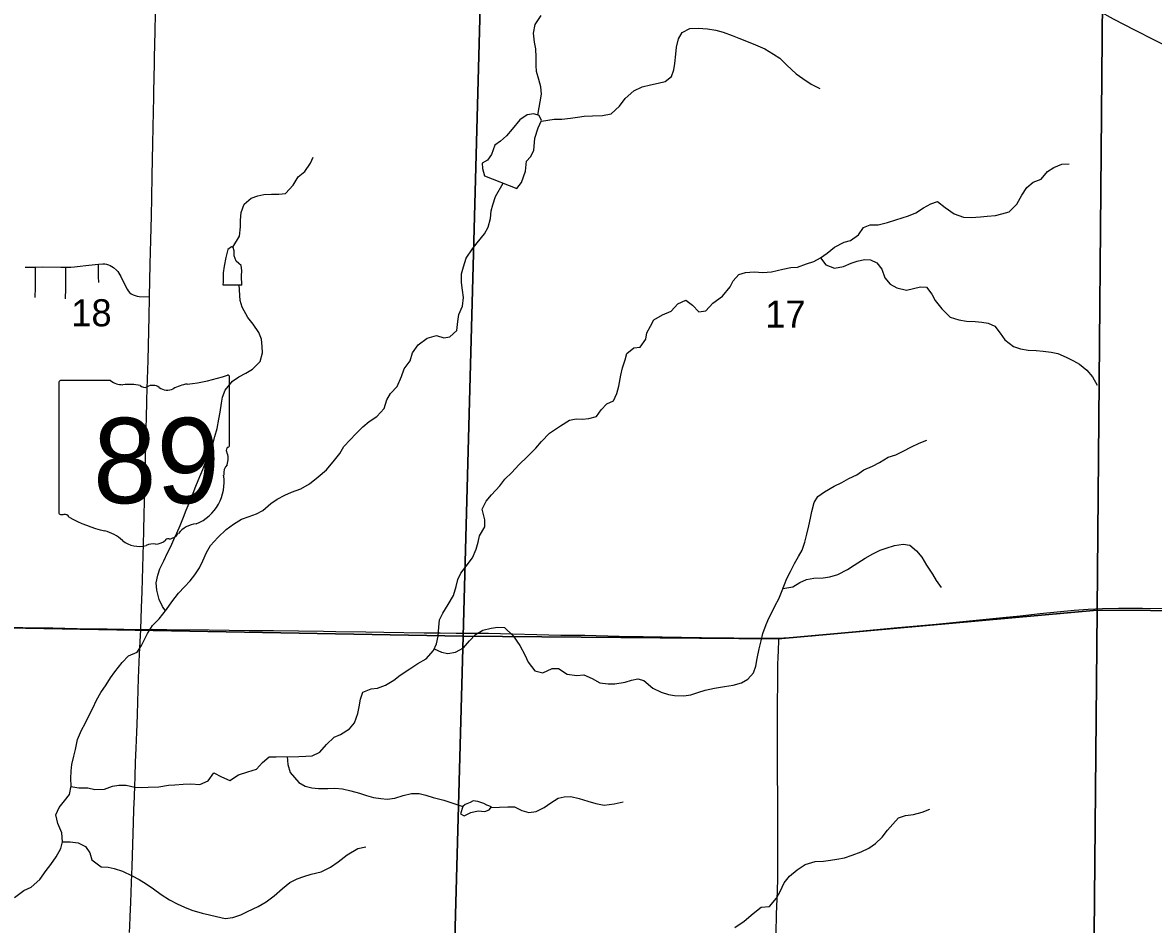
# Model space of a CAD drawing. Extents: x 0 to 34, y 0 to 22.
# Drawn here: x 11.919 to 13.666, y 9.788 to 11.182 of the extents above; entities that cross this region are included whole.
import ezdxf

# ---------------------------------------------------------------- set-up
doc = ezdxf.new("R2010")
doc.units = 0
for name, color, linetype in [('GM_X_County_Road', 7, 'Continuous'), ('GM_X_Minor_Lake', 7, 'Continuous'), ('GM_X_Minor_River', 7, 'Continuous'), ('GM_X_Section', 7, 'Continuous'), ('GM_X_Section_Text', 7, 'Continuous'), ('GM_X_State_Route', 7, 'Continuous'), ('GM_X_State_Shield', 7, 'Continuous'), ('GM_X_Township_Road', 7, 'Continuous'), ('GM_X_US_Route', 7, 'Continuous')]:
    doc.layers.add(name, color=color, linetype=linetype)

msp = doc.modelspace()

# ---------------------------------------------------------------- linework, layer by layer
at = {"layer": 'GM_X_County_Road'}
msp.add_lwpolyline([(13.4671, 11.2609), (13.4723, 11.2592), (13.478, 11.2569), (13.4823, 11.2551), (13.4923, 11.2503), (13.506, 11.243), (13.5275, 11.2307), (13.5572, 11.2137), (13.5814, 11.1998), (13.6032, 11.1878), (13.6363, 11.1705), (13.6668, 11.1552), (13.6919, 11.1429), (13.762, 11.1094), (13.8094, 11.0862), (13.843, 11.07), (13.8851, 11.05), (13.9075, 11.0392), (13.9465, 11.0201), (13.9745, 11.0065), (14.0109, 10.989), (14.0473, 10.9715), (14.078, 10.9566), (14.0833, 10.954)], dxfattribs=at)
at = {"layer": 'GM_X_Minor_Lake'}
for points in [[(12.6823, 10.9255), (12.6891, 10.9346), (12.6955, 10.9521), (12.6969, 10.9676), (12.7034, 10.9745), (12.7083, 10.984), (12.7097, 11.0029), (12.715, 11.0193), (12.7203, 11.0303), (12.7168, 11.0383), (12.7081, 11.0409), (12.6979, 11.039), (12.6869, 11.0317), (12.6748, 11.0169), (12.6661, 11.0066), (12.657, 10.9986), (12.6479, 10.9925), (12.6427, 10.9781), (12.6366, 10.969), (12.6287, 10.9644), (12.6291, 10.9564), (12.6321, 10.945)], [(12.6321, 10.945), (12.6823, 10.9255)], [(12.2571, 10.7763), (12.2567, 10.7898), (12.257, 10.7989), (12.2562, 10.8062), (12.2524, 10.8096), (12.2483, 10.8133), (12.2456, 10.8213), (12.2452, 10.8289), (12.244, 10.8342), (12.2414, 10.8353), (12.2357, 10.8311), (12.2323, 10.819), (12.2297, 10.8053), (12.2282, 10.7951), (12.2283, 10.7806)], [(12.2571, 10.7762), (12.2567, 10.7898), (12.257, 10.7989), (12.2562, 10.8062), (12.2524, 10.8096), (12.2483, 10.8133), (12.2456, 10.8213), (12.2452, 10.8289), (12.244, 10.8342), (12.2414, 10.8353), (12.2357, 10.8311), (12.2323, 10.819), (12.2297, 10.8053), (12.2282, 10.7951), (12.2283, 10.7806)], [(12.2283, 10.7806), (12.228, 10.7764), (12.2571, 10.7763)], [(12.61, 9.9768), (12.6024, 9.9736), (12.5986, 9.9705), (12.5952, 9.9592), (12.6009, 9.9558), (12.6108, 9.9611), (12.6225, 9.9638), (12.6324, 9.9627), (12.6392, 9.965), (12.643, 9.9699), (12.6358, 9.9726)], [(12.6358, 9.9726), (12.6309, 9.9752), (12.6265, 9.9766), (12.6217, 9.9781), (12.6144, 9.9789), (12.61, 9.9768)]]:
    msp.add_lwpolyline(points, dxfattribs=at)
at = {"layer": 'GM_X_Minor_River'}
for points in [[(12.7147, 11.0389), (12.7202, 11.0709), (12.719, 11.0823), (12.7159, 11.0936), (12.7125, 11.1062), (12.7117, 11.1156), (12.712, 11.1285), (12.7112, 11.1411), (12.7093, 11.1517), (12.7077, 11.1653), (12.7104, 11.1786), (12.7198, 11.1927)], [(12.72, 11.0296), (12.7396, 11.0326), (12.7518, 11.0327), (12.765, 11.0342), (12.7756, 11.0358), (12.7859, 11.0369), (12.7988, 11.0377), (12.8143, 11.0382), (12.8276, 11.0409), (12.8405, 11.0527), (12.8492, 11.0645), (12.8628, 11.0763), (12.8757, 11.0824), (12.8886, 11.0858), (12.9003, 11.0881), (12.9113, 11.0908), (12.9211, 11.0984), (12.9245, 11.1087), (12.926, 11.1186), (12.9275, 11.133), (12.929, 11.144), (12.932, 11.1565), (12.9376, 11.1664), (12.9494, 11.1725), (12.9623, 11.1729), (12.9767, 11.1722), (12.9896, 11.17), (13.001, 11.167), (13.015, 11.1617), (13.0253, 11.1576), (13.0371, 11.1531), (13.0507, 11.1474), (13.0652, 11.141), (13.0785, 11.1331), (13.0884, 11.127), (13.0994, 11.1161), (13.1138, 11.1028), (13.1237, 11.0956), (13.137, 11.0866), (13.1503, 11.0798)], [(12.2432, 10.8345), (12.2535, 10.8517), (12.2553, 10.8661), (12.2553, 10.8763), (12.2564, 10.8881), (12.2609, 10.901), (12.2715, 10.9102), (12.2817, 10.914), (12.2912, 10.9159), (12.303, 10.9167), (12.3143, 10.9167), (12.3246, 10.9179), (12.3363, 10.9305), (12.3442, 10.9434), (12.3544, 10.9518), (12.3635, 10.9643), (12.3673, 10.9738)], [(12.9309, 10.7471), (12.9434, 10.7528), (12.9533, 10.7449), (12.9632, 10.7347), (12.9742, 10.7362), (12.9848, 10.748), (12.9999, 10.7591), (13.0116, 10.7732), (13.0165, 10.7827), (13.0248, 10.7926), (13.0355, 10.7956), (13.0487, 10.7964), (13.062, 10.7957), (13.0753, 10.7965), (13.0931, 10.8007), (13.1056, 10.8034), (13.1159, 10.8038), (13.1295, 10.8088), (13.1409, 10.8126), (13.1511, 10.8184), (13.1613, 10.8252), (13.173, 10.8347), (13.1878, 10.8424), (13.1977, 10.8451), (13.2098, 10.8538), (13.2177, 10.8649), (13.228, 10.8691), (13.2405, 10.8691), (13.2549, 10.8726), (13.2674, 10.8768), (13.2776, 10.8798), (13.2871, 10.8829), (13.2985, 10.8879), (13.3106, 10.8955), (13.3216, 10.9016), (13.3318, 10.9054), (13.344, 10.896), (13.3576, 10.8861), (13.3721, 10.8809), (13.3842, 10.8805), (13.3983, 10.8817), (13.4085, 10.8825), (13.4218, 10.8837), (13.4312, 10.886), (13.4426, 10.8894), (13.4547, 10.9012), (13.4623, 10.9149), (13.4698, 10.9267), (13.48, 10.9351), (13.4922, 10.9397), (13.502, 10.9518), (13.5118, 10.9579), (13.5243, 10.9629), (13.5353, 10.9633)], [(12.5437, 10.694), (12.5578, 10.6982), (12.5692, 10.6948), (12.5786, 10.6963), (12.5892, 10.7062), (12.5907, 10.7199), (12.5926, 10.7305), (12.5982, 10.7438), (12.5997, 10.7571), (12.5981, 10.7681), (12.5966, 10.7799), (12.5966, 10.7935), (12.5996, 10.8045), (12.6037, 10.8178), (12.6135, 10.8319), (12.6207, 10.8414), (12.632, 10.8551), (12.6377, 10.8654), (12.6414, 10.879), (12.6425, 10.8908), (12.6448, 10.9003), (12.6493, 10.9128), (12.6612, 10.9337)], [(13.1511, 10.8184), (13.1595, 10.8074), (13.1731, 10.8025), (13.1868, 10.8048), (13.1985, 10.8098), (13.208, 10.8132), (13.219, 10.8159), (13.2285, 10.8152), (13.238, 10.8107), (13.246, 10.8008), (13.2506, 10.7875), (13.2586, 10.7773), (13.2692, 10.7717), (13.284, 10.7683), (13.295, 10.7706), (13.3056, 10.7733), (13.3151, 10.7729), (13.3231, 10.7623), (13.3285, 10.7521), (13.3387, 10.7392), (13.3513, 10.7268), (13.365, 10.7226), (13.3767, 10.7204), (13.39, 10.7197), (13.4006, 10.7189), (13.4105, 10.7175), (13.4208, 10.7126), (13.4288, 10.702), (13.436, 10.6917), (13.4493, 10.6811), (13.4603, 10.6774), (13.4721, 10.6755), (13.4842, 10.6748), (13.4952, 10.6741), (13.5077, 10.6726), (13.518, 10.6704), (13.5309, 10.6647), (13.5419, 10.659), (13.5514, 10.6538), (13.5625, 10.6447), (13.5716, 10.6341), (13.5785, 10.6216)], [(12.1395, 10.2727), (12.1349, 10.2795), (12.1295, 10.2905), (12.1261, 10.3045), (12.1249, 10.3159), (12.1272, 10.328), (12.1305, 10.3375), (12.1366, 10.3501), (12.1422, 10.3622), (12.1475, 10.3721), (12.1524, 10.3828), (12.1569, 10.3926), (12.1618, 10.4048), (12.1671, 10.4173), (12.1712, 10.4284), (12.1761, 10.439), (12.1822, 10.4546), (12.1863, 10.4652), (12.1923, 10.4804), (12.1969, 10.491), (12.2018, 10.5036), (12.207, 10.515), (12.2112, 10.526), (12.2153, 10.5423), (12.2191, 10.5545), (12.2217, 10.5689), (12.2235, 10.5799), (12.2258, 10.5936), (12.2276, 10.6031), (12.2314, 10.6137), (12.2427, 10.6278), (12.2526, 10.6343), (12.2632, 10.64), (12.2738, 10.6461), (12.2855, 10.6579), (12.2889, 10.6712), (12.2885, 10.6814), (12.2877, 10.6928), (12.2835, 10.7026), (12.2747, 10.7159), (12.2663, 10.7261), (12.2576, 10.742), (12.2545, 10.7523), (12.2533, 10.7763)], [(11.9932, 10.0011), (12.0056, 9.9991), (12.0193, 9.9995), (12.0299, 9.9965), (12.0451, 9.9973), (12.0572, 10.0019), (12.067, 10.0034), (12.0784, 10.0035), (12.0917, 10.0005), (12.1023, 9.9998), (12.1126, 10.0002), (12.1289, 10.001), (12.1437, 10.0033), (12.1539, 10.0041), (12.1668, 10.0049), (12.1786, 10.0053), (12.1922, 10.0042), (12.2051, 10.0103), (12.2142, 10.0225), (12.2256, 10.0161), (12.2389, 10.0104), (12.2521, 10.0192), (12.2665, 10.0242), (12.2798, 10.028), (12.2892, 10.0383), (12.2994, 10.047), (12.3101, 10.0474), (12.3453, 10.0476), (12.356, 10.048), (12.3658, 10.0488), (12.3779, 10.0545), (12.3882, 10.0663), (12.3999, 10.0773), (12.4097, 10.0819), (12.4237, 10.0903), (12.4313, 10.0998), (12.4366, 10.1142), (12.4384, 10.1245), (12.4403, 10.1363), (12.4441, 10.1469), (12.4569, 10.1522), (12.4668, 10.1534), (12.4793, 10.158), (12.4918, 10.1656), (12.5016, 10.1732), (12.5168, 10.1832), (12.5289, 10.1912), (12.5418, 10.1988), (12.5531, 10.2113), (12.558, 10.222), (12.5603, 10.2338), (12.5614, 10.2474), (12.5628, 10.2588), (12.5677, 10.2694), (12.5761, 10.2824), (12.5844, 10.2964), (12.5881, 10.3105), (12.5907, 10.3211), (12.5956, 10.331), (12.6039, 10.3416), (12.6134, 10.3546), (12.6194, 10.3683), (12.6224, 10.3789), (12.6243, 10.3888), (12.6326, 10.4024), (12.6326, 10.4134), (12.6287, 10.4301), (12.6348, 10.4423), (12.6431, 10.4522), (12.6559, 10.4659), (12.6635, 10.4761), (12.6745, 10.4864), (12.685, 10.4982), (12.6987, 10.5112), (12.7115, 10.5241), (12.7202, 10.5344), (12.7327, 10.5473), (12.7497, 10.5587), (12.7634, 10.5675), (12.7736, 10.5694), (12.7835, 10.5691), (12.7933, 10.5699), (12.8051, 10.5733), (12.8123, 10.5832), (12.821, 10.5927), (12.8316, 10.5973), (12.8368, 10.6087), (12.8398, 10.6201), (12.8425, 10.6368), (12.8451, 10.6482), (12.8492, 10.6607), (12.8522, 10.6702), (12.8628, 10.679), (12.8727, 10.6802), (12.8814, 10.6927), (12.8828, 10.7022), (12.8885, 10.7128), (12.8938, 10.7223), (12.907, 10.73), (12.9203, 10.7357), (12.9309, 10.7471)], [(11.906, 9.8299), (11.9203, 9.8406), (11.9317, 9.8459), (11.9449, 9.8578), (11.9548, 9.8714), (11.9623, 9.8809), (11.9703, 9.8924), (11.9778, 9.9057), (11.9804, 9.9159), (11.9789, 9.9299), (11.9731, 9.9443), (11.9701, 9.9576), (11.975, 9.969), (11.9833, 9.9793), (11.9908, 9.9892), (11.9935, 10.0025), (11.993, 10.0138), (11.9938, 10.0252), (11.9945, 10.0351), (11.9979, 10.0484), (12.0005, 10.0583), (12.0035, 10.0738), (12.0095, 10.0883), (12.0152, 10.0989), (12.0212, 10.1114), (12.0269, 10.1221), (12.0329, 10.1346), (12.0393, 10.1468), (12.0476, 10.1586), (12.0544, 10.1692), (12.0612, 10.1787), (12.0722, 10.1928), (12.082, 10.2031), (12.0953, 10.2088), (12.1021, 10.2191), (12.1115, 10.2377), (12.1194, 10.2499), (12.1296, 10.2605), (12.141, 10.2746), (12.1493, 10.2868), (12.1595, 10.3001), (12.1686, 10.3096), (12.1773, 10.3191), (12.1844, 10.3286), (12.192, 10.3392), (12.1969, 10.3499), (12.2025, 10.3628), (12.209, 10.3738), (12.2199, 10.386), (12.2328, 10.3986), (12.2441, 10.4069), (12.2566, 10.4146), (12.2684, 10.4184), (12.2798, 10.4226), (12.2896, 10.428), (12.3021, 10.4386), (12.3119, 10.4455), (12.3237, 10.4516), (12.3339, 10.4562), (12.3483, 10.4611), (12.3619, 10.4692), (12.3752, 10.4798), (12.388, 10.4905), (12.4005, 10.5057), (12.4085, 10.516), (12.4149, 10.5266), (12.4247, 10.5369), (12.4334, 10.5464), (12.4444, 10.5571), (12.4542, 10.5651), (12.4656, 10.5731), (12.4769, 10.5856), (12.481, 10.5989), (12.4871, 10.6088), (12.4973, 10.6194), (12.5037, 10.635), (12.5078, 10.6468), (12.5173, 10.6593), (12.5207, 10.6715), (12.5297, 10.6837), (12.5437, 10.694)], [(12.5543, 10.2138), (12.5656, 10.2087), (12.5755, 10.2069), (12.5873, 10.2088), (12.5998, 10.2157), (12.6092, 10.2263), (12.6183, 10.2362), (12.6293, 10.2431), (12.6425, 10.2458), (12.6528, 10.2473), (12.663, 10.247), (12.6763, 10.2341), (12.6866, 10.219), (12.6946, 10.2046), (12.6996, 10.1932), (12.7099, 10.18), (12.722, 10.177), (12.7368, 10.1838), (12.7463, 10.1835), (12.76, 10.1748), (12.7748, 10.1729), (12.7854, 10.1737), (12.7987, 10.1681), (12.8101, 10.1617), (12.823, 10.1598), (12.8336, 10.1598), (12.8492, 10.1625), (12.8594, 10.1656), (12.8689, 10.1675), (12.8784, 10.1653), (12.892, 10.1532), (12.905, 10.1472), (12.9164, 10.1434), (12.9258, 10.1419), (12.9399, 10.1412), (12.9509, 10.1431), (12.9615, 10.1466), (12.9732, 10.1504), (12.9873, 10.1535), (13.0028, 10.1558), (13.0161, 10.1577), (13.029, 10.1616), (13.0388, 10.1673), (13.0475, 10.1772), (13.0513, 10.1874), (13.0535, 10.1992), (13.0565, 10.214), (13.0595, 10.2262), (13.0621, 10.2379), (13.0674, 10.2516), (13.0715, 10.2615), (13.0768, 10.2714), (13.081, 10.2809), (13.0866, 10.2911), (13.0908, 10.3014), (13.0957, 10.3132), (13.0994, 10.3227), (13.1047, 10.3333), (13.1111, 10.3458), (13.1172, 10.3565), (13.1228, 10.3664), (13.127, 10.3789), (13.1303, 10.3911), (13.1333, 10.4043), (13.136, 10.4161), (13.1378, 10.426), (13.1412, 10.44), (13.1469, 10.4495), (13.1575, 10.4568), (13.1722, 10.4652), (13.1844, 10.4713), (13.195, 10.477), (13.2071, 10.4831), (13.2184, 10.4904), (13.2317, 10.4965), (13.2423, 10.5022), (13.2559, 10.5102), (13.2677, 10.514), (13.2802, 10.5198), (13.2908, 10.5255), (13.3037, 10.5316), (13.3154, 10.5366)], [(13.0932, 10.3073), (13.1086, 10.3098), (13.1192, 10.3163), (13.1294, 10.3212), (13.1408, 10.3232), (13.1552, 10.3236), (13.1658, 10.3251), (13.1779, 10.329), (13.1931, 10.3366), (13.2033, 10.3431), (13.22, 10.3541), (13.2321, 10.3606), (13.2435, 10.3664), (13.2529, 10.3694), (13.2658, 10.3736), (13.2787, 10.3756), (13.2893, 10.3741), (13.2996, 10.3654), (13.3076, 10.3555), (13.3152, 10.3434), (13.324, 10.3294), (13.3301, 10.3196), (13.3377, 10.309)], [(12.3275, 10.0475), (12.3283, 10.0354), (12.3321, 10.0229), (12.3451, 10.0073), (12.355, 10.0017), (12.3656, 9.9994), (12.3758, 9.9983), (12.3899, 9.9984), (12.4009, 9.9988), (12.413, 9.9977), (12.4255, 9.9947), (12.4388, 9.9909), (12.4498, 9.9875), (12.4605, 9.9842), (12.4719, 9.9827), (12.4817, 9.9816), (12.4935, 9.9835), (12.5064, 9.9873), (12.5192, 9.9904), (12.531, 9.9904), (12.5416, 9.9878), (12.553, 9.9844), (12.5694, 9.9803), (12.5986, 9.9706)], [(12.6422, 9.9689), (12.668, 9.97), (12.6786, 9.9697), (12.69, 9.964), (12.7007, 9.961), (12.7117, 9.9625), (12.7242, 9.9687), (12.7348, 9.9763), (12.7457, 9.9831), (12.7552, 9.9854), (12.7655, 9.9859), (12.7784, 9.9829), (12.7917, 9.9787), (12.8042, 9.975), (12.8171, 9.9724), (12.8326, 9.9747), (12.8463, 9.9778)], [(13.0191, 9.7833), (13.0335, 9.7932), (13.0471, 9.805), (13.0596, 9.8149), (13.0725, 9.816), (13.0834, 9.829), (13.0887, 9.8392), (13.0951, 9.8522), (13.1034, 9.8628), (13.1152, 9.8727), (13.1273, 9.8807), (13.1428, 9.8853), (13.1561, 9.8857), (13.1667, 9.8873), (13.1762, 9.8888), (13.1883, 9.8911), (13.2001, 9.895), (13.2141, 9.9003), (13.2258, 9.9061), (13.2364, 9.9133), (13.2467, 9.9228), (13.2546, 9.9338), (13.2629, 9.9433), (13.2716, 9.9529), (13.2826, 9.9567), (13.2947, 9.9579), (13.3084, 9.9617), (13.3201, 9.9663)], [(11.9804, 9.9159), (11.9918, 9.9156), (12.0043, 9.9145), (12.0157, 9.9088), (12.0226, 9.8986), (12.0257, 9.888), (12.0397, 9.8774), (12.0507, 9.8767), (12.0602, 9.8748), (12.0731, 9.8703), (12.0876, 9.8635), (12.0986, 9.8578), (12.1096, 9.851), (12.121, 9.8431), (12.1324, 9.8344), (12.1453, 9.8261), (12.1575, 9.8201), (12.1685, 9.8148), (12.1799, 9.8103), (12.1958, 9.8058), (12.2072, 9.8028), (12.2182, 9.8005), (12.2315, 9.7975), (12.2433, 9.7987), (12.2558, 9.8029), (12.266, 9.8083), (12.2827, 9.8159), (12.2948, 9.8232), (12.3073, 9.8323), (12.3201, 9.8437), (12.3315, 9.8532), (12.3425, 9.8586), (12.3531, 9.8624), (12.3645, 9.8659), (12.38, 9.8697), (12.394, 9.8766), (12.4061, 9.885), (12.4198, 9.8956), (12.4364, 9.9055), (12.4489, 9.9082)]]:
    msp.add_lwpolyline(points, dxfattribs=at)
at = {"layer": 'GM_X_Section'}
for points in [[(12.6265, 11.2451), (13.123, 11.237), (13.5876, 11.2769), (13.5789, 10.274), (13.086, 10.2295), (12.599, 10.2335)], [(13.5876, 11.2769), (14.5738, 11.2682), (14.5701, 10.2676), (13.5789, 10.274)], [(11.591, 11.2544), (12.6265, 11.2451), (12.599, 10.2335), (11.5847, 10.2523), (11.5843, 10.269)], [(12.599, 10.2335), (13.086, 10.2295), (13.5789, 10.274), (13.5692, 9.2712), (13.0735, 9.2573), (12.5724, 9.2601)], [(13.5789, 10.274), (14.5701, 10.2676), (14.5716, 9.2663), (13.5692, 9.2712)], [(12.599, 10.2335), (12.5724, 9.2601), (11.5779, 9.2661), (11.5847, 10.2523)]]:
    msp.add_lwpolyline(points, close=True, dxfattribs=at)
at = {"layer": 'GM_X_State_Route'}
for points in [[(12.101, 10.2441), (12.1024, 10.2775), (12.1034, 10.3024), (12.1049, 10.3583), (12.1057, 10.3956), (12.1063, 10.4235), (12.1067, 10.4391), (12.1076, 10.4733), (12.1084, 10.5075), (12.1089, 10.5292), (12.1094, 10.5572), (12.1098, 10.5696), (12.1107, 10.5976), (12.1112, 10.6162), (12.1125, 10.6597), (12.114, 10.7281), (12.1146, 10.7561), (12.1147, 10.7578), (12.1157, 10.8083), (12.1167, 10.8456), (12.1175, 10.8829), (12.1181, 10.9108), (12.1188, 10.945), (12.1198, 10.9947), (12.1207, 11.0443), (12.1211, 11.066), (12.1214, 11.0751), (12.1217, 11.0966), (12.1221, 11.1183), (12.1224, 11.1276), (12.1232, 11.1679), (12.1237, 11.1959)], [(12.0955, 10.0971), (12.0961, 10.113), (12.0978, 10.1688), (12.0992, 10.206), (12.101, 10.2441)], [(12.0905, 9.9676), (12.0907, 9.9737), (12.0918, 10.0015), (12.0924, 10.017), (12.0932, 10.0387), (12.094, 10.0604), (12.0951, 10.0851), (12.0955, 10.0971)], [(12.0839, 9.7757), (12.0839, 9.7767), (12.0842, 9.7848), (12.0848, 9.8003), (12.0856, 9.822), (12.0867, 9.8529), (12.0876, 9.8777), (12.0886, 9.9118), (12.0897, 9.9459), (12.0903, 9.9645), (12.0905, 9.9676)]]:
    msp.add_lwpolyline(points, dxfattribs=at)
at = {"layer": 'GM_X_State_Shield'}
for p, q in [((11.9747, 10.6251), (11.9747, 10.425)), ((12.0545, 10.6285), (11.9773, 10.6285)), ((12.2383, 10.5288), (12.2383, 10.6335)), ((12.2383, 10.5288), (12.2383, 10.5288))]:
    msp.add_line(p, q, dxfattribs=at)
for centre, radius, start, end in [((11.9777, 10.6255), 0.00305, 98.1301, 188.1301), ((12.0729, 10.6518), 0.0296, 231.6195, 271.1119), ((12.0827, 10.5162), 0.1064, 80.4867, 94.9883), ((12.1801, 10.5674), 0.0563, 97.3462, 120.7689), ((12.1444, 10.9014), 0.2796, 275.8445, 288.9065), ((12.2354, 10.6339), 0.00294, 351.8621, 97.738), ((12.1068, 10.6266), 0.00855, 219.7921, 297.1024), ((12.1194, 10.6034), 0.0178, 54.4667, 119.1411), ((12.1423, 10.6352), 0.0214, 233.8562, 294.8282), ((12.2377, 10.5211), 0.00454, 107.944, 210.337), ((12.2088, 10.5079), 0.0273, 340.033, 23.6496), ((12.2352, 10.5284), 0.00314, 289.6038, 7.7341), ((12.1601, 10.4717), 0.0699, 292.3089, 8.9858), ((12.2489, 10.485), 0.0198, 136.8065, 186.9296), ((11.9777, 10.4245), 0.00308, 171.9584, 258.3066), ((11.9782, 10.445), 0.0235, 267.339, 280.6039), ((11.983, 10.4134), 0.00848, 29.7484, 93.2717), ((12.0901, 10.5932), 0.2019, 240.4129, 257.1985), ((12.0299, 10.3351), 0.0632, 47.1842, 75.836), ((12.1896, 10.3688), 0.0383, 94.4031, 142.5768), ((12.0982, 10.4124), 0.0401, 230.7004, 286.2918), ((12.1243, 10.3974), 0.0214, 268.777, 315.5493), ((12.1436, 10.3781), 0.00601, 65.7517, 132.6484), ((12.141, 10.4056), 0.0226, 282.8732, 323.2771), ((12.1214, 10.3432), 0.0329, 85.6951, 111.2099)]:
    msp.add_arc(centre, radius, start, end, dxfattribs=at)
at = {"layer": 'GM_X_Township_Road'}
for points in [[(11.9224, 10.8036), (11.9297, 10.8037), (11.9363, 10.8038), (11.9383, 10.8039)], [(11.9381, 10.7571), (11.9384, 10.7723), (11.9386, 10.7844), (11.9384, 10.7965), (11.9383, 10.8039)], [(11.9383, 10.8039), (11.95, 10.8041), (11.9778, 10.8038), (11.9855, 10.8037)], [(11.9849, 10.7549), (11.9853, 10.7706), (11.9854, 10.7955), (11.9855, 10.8037)], [(11.9855, 10.8037), (11.9875, 10.8037), (11.9929, 10.804), (11.9985, 10.8044), (12.0028, 10.8047), (12.021, 10.8067), (12.0358, 10.8084)], [(12.0361, 10.7801), (12.0357, 10.7893), (12.0358, 10.8015), (12.0358, 10.8084)], [(12.0358, 10.8084), (12.0424, 10.8089), (12.0454, 10.8088), (12.0483, 10.8084), (12.0512, 10.8075), (12.0539, 10.8064), (12.0566, 10.8049), (12.059, 10.8032), (12.0635, 10.7992), (12.0655, 10.797), (12.0673, 10.7946), (12.0703, 10.7893), (12.077, 10.7754), (12.08, 10.7699), (12.0818, 10.7673), (12.0839, 10.7649), (12.0864, 10.7628), (12.0892, 10.7612), (12.0922, 10.76), (12.0953, 10.7592), (12.0984, 10.7587), (12.1147, 10.7578)], [(13.0827, 9.7742), (13.0834, 9.8041), (13.0846, 9.8395), (13.0851, 9.8594), (13.0854, 9.8921), (13.0855, 9.9108), (13.0855, 9.9574), (13.0848, 10.0475), (13.0848, 10.1158), (13.0848, 10.1345), (13.0851, 10.1562), (13.0854, 10.1903), (13.0858, 10.2005), (13.0862, 10.2115), (13.0867, 10.2268), (13.0871, 10.2307)]]:
    msp.add_lwpolyline(points, dxfattribs=at)
at = {"layer": 'GM_X_US_Route'}
for points in [[(12.101, 10.2441), (12.1196, 10.2445), (12.1414, 10.244), (12.2066, 10.2433), (12.2687, 10.2425), (12.3059, 10.2422), (12.3836, 10.2412), (12.4022, 10.241), (12.4488, 10.2403), (12.4768, 10.2399), (12.5389, 10.2388), (12.5638, 10.2386), (12.5886, 10.2384), (12.6383, 10.238), (12.6756, 10.2374), (12.7128, 10.2362), (12.7501, 10.2354), (12.7873, 10.235), (12.8401, 10.2338), (12.8773, 10.233), (12.9363, 10.2319), (12.9674, 10.2315), (12.9954, 10.2312), (13.0171, 10.2308), (13.0513, 10.2304), (13.0668, 10.2305), (13.0797, 10.2304), (13.0871, 10.2307), (13.1103, 10.2322), (13.1383, 10.2341), (13.2001, 10.2401), (13.265, 10.2464), (13.33, 10.2524), (13.4382, 10.2631), (13.4599, 10.2652), (13.4908, 10.2684), (13.5433, 10.2737), (13.565, 10.2754), (13.5867, 10.2764), (13.6115, 10.277), (13.6488, 10.277), (13.711, 10.2766)], [(11.5886, 10.2585), (11.5897, 10.2583), (11.6082, 10.2558), (11.6236, 10.2543), (11.6422, 10.2532), (11.6795, 10.2519), (11.7416, 10.2501), (11.7882, 10.2492), (11.8628, 10.2482), (11.8877, 10.2477), (11.9188, 10.247), (11.9654, 10.2464), (12.0027, 10.2456), (12.0276, 10.2452), (12.0493, 10.245), (12.101, 10.2441)]]:
    msp.add_lwpolyline(points, dxfattribs=at)

# ---------------------------------------------------------------- texts
at = {"layer": 'GM_X_Section_Text'}
for s, p in [('18', (11.9938, 10.7124)), ('17', (13.0659, 10.7104))]:
    msp.add_text(s, height=0.04186, rotation=0, dxfattribs=at).set_placement(p)
at = {"layer": 'GM_X_State_Shield'}
msp.add_text('89', height=0.13184, dxfattribs=at).set_placement((12.0273, 10.4391))

doc.saveas('drawing.dxf')
